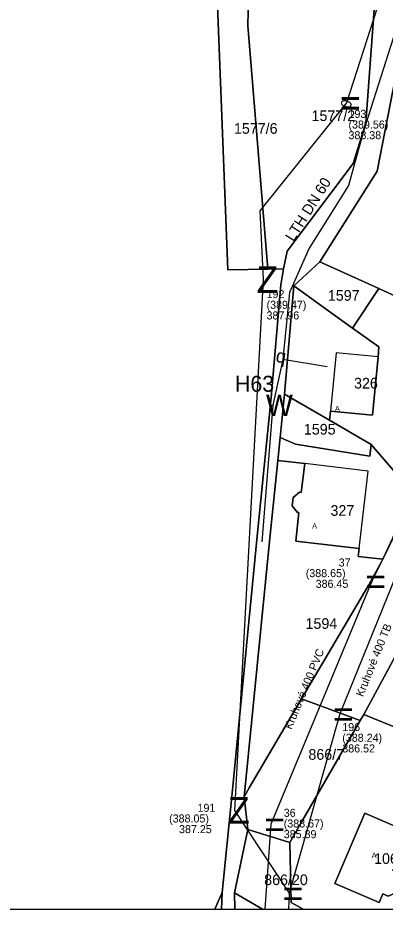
# Model space of a CAD drawing. Extents: x -564940 to -564406, y -1066466 to -1066072.
# Drawn here: x -564826.1 to -564757.1, y -1066465.6 to -1066298.6 of the extents above; entities that cross this region are included whole.
import ezdxf

# ---------------------------------------------------------------- set-up
doc = ezdxf.new("R2010")
doc.units = 0
for name, color, linetype in [('ft_g_5211', 7, 'Continuous'), ('ft_g_5411', 7, 'Continuous'), ('ft_g_5451', 7, 'Continuous'), ('ft_g_5451_ft_g_5451_da_5452_gtc_da_5452', 7, 'Continuous'), ('ft_g_6031', 7, 'Continuous'), ('ft_g_6101', 7, 'Continuous'), ('ft_g_6101_ft_g_6101_da_6108_gtc_da_6108', 7, 'Continuous'), ('ft_g_stoka', 7, 'Continuous'), ('ft_g_stoka_ft_g_stoka_da_popis_gtc_da_6004', 7, 'Continuous'), ('ft_g_vrad', 7, 'Continuous'), ('ft_g_vrad_ft_g_vrad_da_popis_gtc_da_5091', 7, 'Continuous'), ('ft_parcela_polygon', 7, 'Continuous'), ('ft_parcela_text', 7, 'Continuous'), ('ft_stavebni_objekt_bod', 7, 'Continuous'), ('ft_stavebni_objekt_polygon', 7, 'Continuous')]:
    doc.layers.add(name, color=color, linetype=linetype)

msp = doc.modelspace()

# ---------------------------------------------------------------- linework, layer by layer
at = {"layer": 'ft_g_5211'}
msp.add_line((-564768.03, -1066364.03), (-564776.33, -1066362.66), dxfattribs=at)
at = {"layer": 'ft_g_stoka'}
for p, q in [((-564732.02, -1066213.94), (-564764.38, -1066314.56)), ((-564764.38, -1066314.56), (-564780.67, -1066334.78)), ((-564780.67, -1066334.78), (-564780.03, -1066347.69)), ((-564780.03, -1066347.69), (-564785.42, -1066447.12)), ((-564737.98, -1066360.23), (-564759.65, -1066404.2)), ((-564751.59, -1066394.32), (-564765.68, -1066429.05)), ((-564759.65, -1066404.2), (-564778.61, -1066449.72)), ((-564765.68, -1066429.05), (-564775.14, -1066462.65)), ((-564785.42, -1066447.12), (-564775.14, -1066462.65)), ((-564778.61, -1066449.72), (-564779.71, -1066465.63)), ((-564775.14, -1066462.65), (-564775.28, -1066465.63))]:
    msp.add_line(p, q, dxfattribs=at)
at = {"layer": 'ft_g_vrad'}
msp.add_line((-564778.51, -1066371.24), (-564778.22, -1066371.24), dxfattribs=at)
msp.add_lwpolyline([(-564739.36, -1066244.92), (-564746.76, -1066274.62), (-564761.24, -1066319.9), (-564764.01, -1066330.07), (-564771.4, -1066341.78), (-564775.1, -1066350.1), (-564776.33, -1066362.64), (-564778.21, -1066371.22), (-564780.31, -1066396.81)], dxfattribs=at)
at = {"layer": 'ft_parcela_polygon'}
for p, q in [((-564829.56, -1066465.63), (-564789.13, -1066465.63)), ((-564789.13, -1066465.63), (-564787.89, -1066465.63)), ((-564787.89, -1066465.63), (-564785.39, -1066465.63)), ((-564785.39, -1066465.63), (-564780.19, -1066465.63)), ((-564780.19, -1066465.63), (-564772.54, -1066465.63)), ((-564772.54, -1066465.63), (-564741.9, -1066465.63))]:
    msp.add_line(p, q, dxfattribs=at)
for points in [[(-564789.13, -1066465.63), (-564787.74, -1066462.49), (-564785.83, -1066443.87), (-564781.17, -1066395.78), (-564778.57, -1066369.76), (-564776.75, -1066348.66), (-564776.2, -1066345.68), (-564779.17, -1066345.72), (-564786.65, -1066345.83), (-564788.66, -1066294.62), (-564786.51, -1066194.35), (-564785.71, -1066194.37), (-564785.51, -1066187.08), (-564780.98, -1066187.19), (-564781.14, -1066194.46), (-564776.02, -1066194.57), (-564768.77, -1066194.68), (-564751.79, -1066195.2)], [(-564735.99, -1066241.09), (-564758.45, -1066286.89), (-564759.08, -1066295.42), (-564760.78, -1066318.3), (-564763.14, -1066325.95), (-564775.57, -1066342.33), (-564776.2, -1066345.68), (-564776.75, -1066348.66), (-564778.57, -1066369.76), (-564781.17, -1066395.78), (-564785.83, -1066443.87), (-564787.74, -1066462.49), (-564787.89, -1066465.63)], [(-564785.39, -1066465.63), (-564785.41, -1066462.6), (-564782.94, -1066450.71), (-564783.58, -1066444.58), (-564778.8, -1066396.1), (-564777.32, -1066381.57), (-564776.88, -1066377.29), (-564776.05, -1066369.13), (-564774.26, -1066348.88), (-564769.4, -1066344.34), (-564758.63, -1066327.35), (-564754.76, -1066307.54)], [(-564741.9, -1066465.63), (-564728.11, -1066442.62), (-564729.04, -1066442.24), (-564761.15, -1066429.16), (-564761.84, -1066430.27), (-564773.02, -1066449.63), (-564775.06, -1066453.15), (-564774.81, -1066464.4), (-564772.54, -1066465.63)], [(-564760.96, -1066447.66), (-564751.73, -1066451.62), (-564753.39, -1066455.44), (-564754.77, -1066458.83), (-564754.2, -1066460.37), (-564755.14, -1066462.59), (-564756.61, -1066463.17), (-564757.6, -1066462.76), (-564758.3, -1066464.37), (-564766.61, -1066460.8), (-564760.96, -1066447.66)], [(-564772.54, -1066465.63), (-564774.81, -1066464.4), (-564775.06, -1066453.15), (-564782.94, -1066450.71), (-564785.41, -1066462.6), (-564780.19, -1066465.63)], [(-564787.89, -1066465.63), (-564787.74, -1066462.49), (-564789.13, -1066465.63)], [(-564780.19, -1066465.63), (-564785.41, -1066462.6), (-564785.39, -1066465.63)]]:
    msp.add_lwpolyline(points, dxfattribs=at)
for points in [[(-564786.65, -1066345.83), (-564779.17, -1066345.72), (-564782.89, -1066300.08), (-564782.77, -1066294.78), (-564788.66, -1066294.62)], [(-564763.14, -1066325.95), (-564760.78, -1066318.3), (-564759.08, -1066295.42), (-564778.35, -1066294.84), (-564782.77, -1066294.78), (-564782.89, -1066300.08), (-564779.17, -1066345.72), (-564776.2, -1066345.68), (-564775.57, -1066342.33)], [(-564758.63, -1066327.35), (-564769.4, -1066344.34), (-564758.34, -1066349.33), (-564744.59, -1066355.75), (-564728.86, -1066323.53), (-564740.69, -1066316.86), (-564736.92, -1066310.24), (-564741.53, -1066307.59), (-564742.46, -1066310.95), (-564753.52, -1066307.88), (-564754.76, -1066307.54)], [(-564765.74, -1066355.01), (-564763.26, -1066356.76), (-564758.34, -1066349.33), (-564769.4, -1066344.34), (-564774.26, -1066348.88)], [(-564759.55, -1066373.09), (-564758.49, -1066362.14), (-564758.31, -1066360.26), (-564763.26, -1066356.76), (-564765.74, -1066355.01), (-564774.26, -1066348.88), (-564776.05, -1066369.13), (-564767.58, -1066374.04), (-564767.41, -1066372.33)], [(-564758.34, -1066349.33), (-564763.26, -1066356.76), (-564758.31, -1066360.26), (-564758.49, -1066362.14), (-564759.55, -1066373.09), (-564767.41, -1066372.33), (-564767.58, -1066374.04), (-564759.75, -1066378.58), (-564752.48, -1066387.1), (-564750.23, -1066383.61), (-564746.85, -1066382.26), (-564737.04, -1066362.92), (-564739.99, -1066360.12), (-564744.59, -1066355.75)], [(-564759.75, -1066378.58), (-564767.58, -1066374.04), (-564776.05, -1066369.13), (-564776.88, -1066377.29), (-564773.99, -1066378.49), (-564760.01, -1066380.77)], [(-564755.71, -1066396.05), (-564752.48, -1066387.1), (-564759.75, -1066378.58), (-564760.01, -1066380.77), (-564773.99, -1066378.49), (-564776.88, -1066377.29), (-564777.32, -1066381.57), (-564772.25, -1066382.16), (-564772.9, -1066387.55), (-564773.22, -1066387.53), (-564774.42, -1066388.48), (-564774.6, -1066390.1), (-564773.61, -1066391.31), (-564773.35, -1066391.34), (-564773.94, -1066396.66), (-564762.02, -1066398.05), (-564762.19, -1066399.54), (-564757.59, -1066400.08)], [(-564757.76, -1066400.45), (-564757.59, -1066400.08), (-564762.19, -1066399.54), (-564762.02, -1066398.05), (-564773.94, -1066396.66), (-564773.35, -1066391.34), (-564773.61, -1066391.31), (-564774.6, -1066390.1), (-564774.42, -1066388.48), (-564773.22, -1066387.53), (-564772.9, -1066387.55), (-564772.25, -1066382.16), (-564777.32, -1066381.57), (-564778.8, -1066396.1), (-564783.58, -1066444.58), (-564782.65, -1066442.93), (-564772.83, -1066426.25), (-564760.24, -1066404.88)], [(-564761.84, -1066430.27), (-564761.15, -1066429.16), (-564750.17, -1066408.79), (-564749.02, -1066406.55), (-564741.77, -1066391), (-564749.44, -1066386.03), (-564750.23, -1066383.61), (-564752.48, -1066387.1), (-564755.71, -1066396.05), (-564757.59, -1066400.08), (-564757.76, -1066400.45), (-564760.24, -1066404.88), (-564772.83, -1066426.25)], [(-564717.41, -1066424.81), (-564749.02, -1066406.55), (-564750.17, -1066408.79), (-564761.15, -1066429.16), (-564729.04, -1066442.24), (-564728.11, -1066442.62)], [(-564773.02, -1066449.63), (-564761.84, -1066430.27), (-564772.83, -1066426.25), (-564782.65, -1066442.93), (-564783.58, -1066444.58), (-564782.94, -1066450.71), (-564775.06, -1066453.15)], [(-564751.73, -1066451.62), (-564760.96, -1066447.66), (-564766.61, -1066460.8), (-564758.3, -1066464.37), (-564757.6, -1066462.76), (-564756.61, -1066463.17), (-564755.14, -1066462.59), (-564754.2, -1066460.37), (-564754.77, -1066458.83), (-564753.39, -1066455.44)]]:
    msp.add_lwpolyline(points, close=True, dxfattribs=at)
at = {"layer": 'ft_stavebni_objekt_polygon'}
for points in [[(-564767.41, -1066372.33), (-564759.55, -1066373.09), (-564758.49, -1066362.14), (-564766.35, -1066361.38)], [(-564774.6, -1066390.1), (-564773.61, -1066391.31), (-564773.35, -1066391.34), (-564773.94, -1066396.66), (-564762.02, -1066398.05), (-564760.33, -1066383.55), (-564772.25, -1066382.16), (-564772.9, -1066387.55), (-564773.22, -1066387.53), (-564774.42, -1066388.48)], [(-564766.61, -1066460.8), (-564758.3, -1066464.37), (-564757.6, -1066462.76), (-564756.61, -1066463.17), (-564755.14, -1066462.59), (-564754.2, -1066460.37), (-564754.77, -1066458.83), (-564755.72, -1066458.41), (-564754.27, -1066455.05), (-564753.39, -1066455.44), (-564751.73, -1066451.62), (-564760.96, -1066447.66)]]:
    msp.add_lwpolyline(points, close=True, dxfattribs=at)

# ---------------------------------------------------------------- texts
at = {"layer": 'ft_g_5411'}
msp.add_text('b', height=2.5, rotation=170.6028, dxfattribs=at).set_placement((-564775.64, -1066361.5))
at = {"layer": 'ft_g_5451'}
msp.add_text('W', height=4, dxfattribs=at).set_placement((-564779.51, -1066373.24))
at = {"layer": 'ft_g_5451_ft_g_5451_da_5452_gtc_da_5452'}
msp.add_text('H63', height=3, dxfattribs=at).set_placement((-564785.34, -1066368.7))
at = {"layer": 'ft_g_6031'}
msp.add_text('0', height=2, rotation=72.169, dxfattribs=at).set_placement((-564763.72, -1066315.77))
at = {"layer": 'ft_g_6101'}
for s, p in [('=', (-564765.63, -1066317.06)), ('Z', (-564781.28, -1066350.19)), ('=', (-564760.9, -1066406.7)), ('Z', (-564786.67, -1066449.62)), ('=', (-564779.86, -1066452.22)), ('=', (-564776.39, -1066465.15))]:
    msp.add_text(s, height=5, dxfattribs=at).set_placement(p)
msp.add_text('=', height=5, rotation=360, dxfattribs=at).set_placement((-564766.93, -1066431.55))
at = {"layer": 'ft_g_6101_ft_g_6101_da_6108_gtc_da_6108'}
for s, p in [('193', (-564764.03, -1066317.38)), ('(389.56)', (-564764.03, -1066319.38)), ('388.38', (-564764.03, -1066321.38)), ('192', (-564779.41, -1066351.15)), ('(389.47)', (-564779.41, -1066353.15)), ('387.96', (-564779.41, -1066355.15)), ('37', (-564765.87, -1066401.43)), ('(388.65)', (-564772.05, -1066403.43)), ('386.45', (-564770.19, -1066405.43)), ('196', (-564765.2, -1066432.27)), ('(388.24)', (-564765.2, -1066434.27)), ('386.52', (-564765.2, -1066436.27)), ('191', (-564792.36, -1066447.39)), ('36', (-564776.18, -1066448.33)), ('(388.05)', (-564797.69, -1066449.39)), ('(388.67)', (-564776.18, -1066450.33)), ('387.25', (-564795.83, -1066451.39)), ('385.89', (-564776.18, -1066452.33))]:
    msp.add_text(s, height=1.5, dxfattribs=at).set_placement(p)
at = {"layer": 'ft_g_stoka_ft_g_stoka_da_popis_gtc_da_6004'}
for s, rotation, p in [('Kruhové 400 TB', 67.9187, (-564761.32, -1066425.96)), ('Kruhové 400 PVC', 67.3873, (-564774.74, -1066432.08))]:
    msp.add_text(s, height=1.5, rotation=rotation, dxfattribs=at).set_placement(p)
at = {"layer": 'ft_g_vrad_ft_g_vrad_da_popis_gtc_da_5091'}
msp.add_text('LTH DN 60', height=2, rotation=57.7386, dxfattribs=at).set_placement((-564774.35, -1066340.7))
at = {"layer": 'ft_parcela_text'}
for s, p in [('1577/2', (-564770.96, -1066317.98)), ('1577/6', (-564785.52, -1066320.37)), ('1597', (-564767.9, -1066351.65)), ('326', (-564762.98, -1066368.09)), ('1595', (-564772.4, -1066376.72)), ('327', (-564767.41, -1066391.94)), ('1594', (-564772.09, -1066413.12)), ('866/7', (-564771.55, -1066437.64)), ('1067', (-564759.22, -1066457.16)), ('866/20', (-564779.85, -1066461.12))]:
    msp.add_text(s, height=2, dxfattribs=at).set_placement(p)
at = {"layer": 'ft_stavebni_objekt_bod'}
for p in [(-564766.58, -1066372.34), (-564770.86, -1066394.34), (-564759.68, -1066456.05)]:
    msp.add_text('A', height=1, dxfattribs=at).set_placement(p)

doc.saveas('drawing.dxf')
